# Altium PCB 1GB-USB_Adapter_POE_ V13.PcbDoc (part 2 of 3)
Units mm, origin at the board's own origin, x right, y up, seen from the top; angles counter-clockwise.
Board outline 92 x 80 mm, 4 copper layers (Top Layer, Signal Layer 2, Signal Layer 3, Bottom Layer), stack 1.57 mm thick; 189 components, 102 nets, 551 pads, 429 vias.
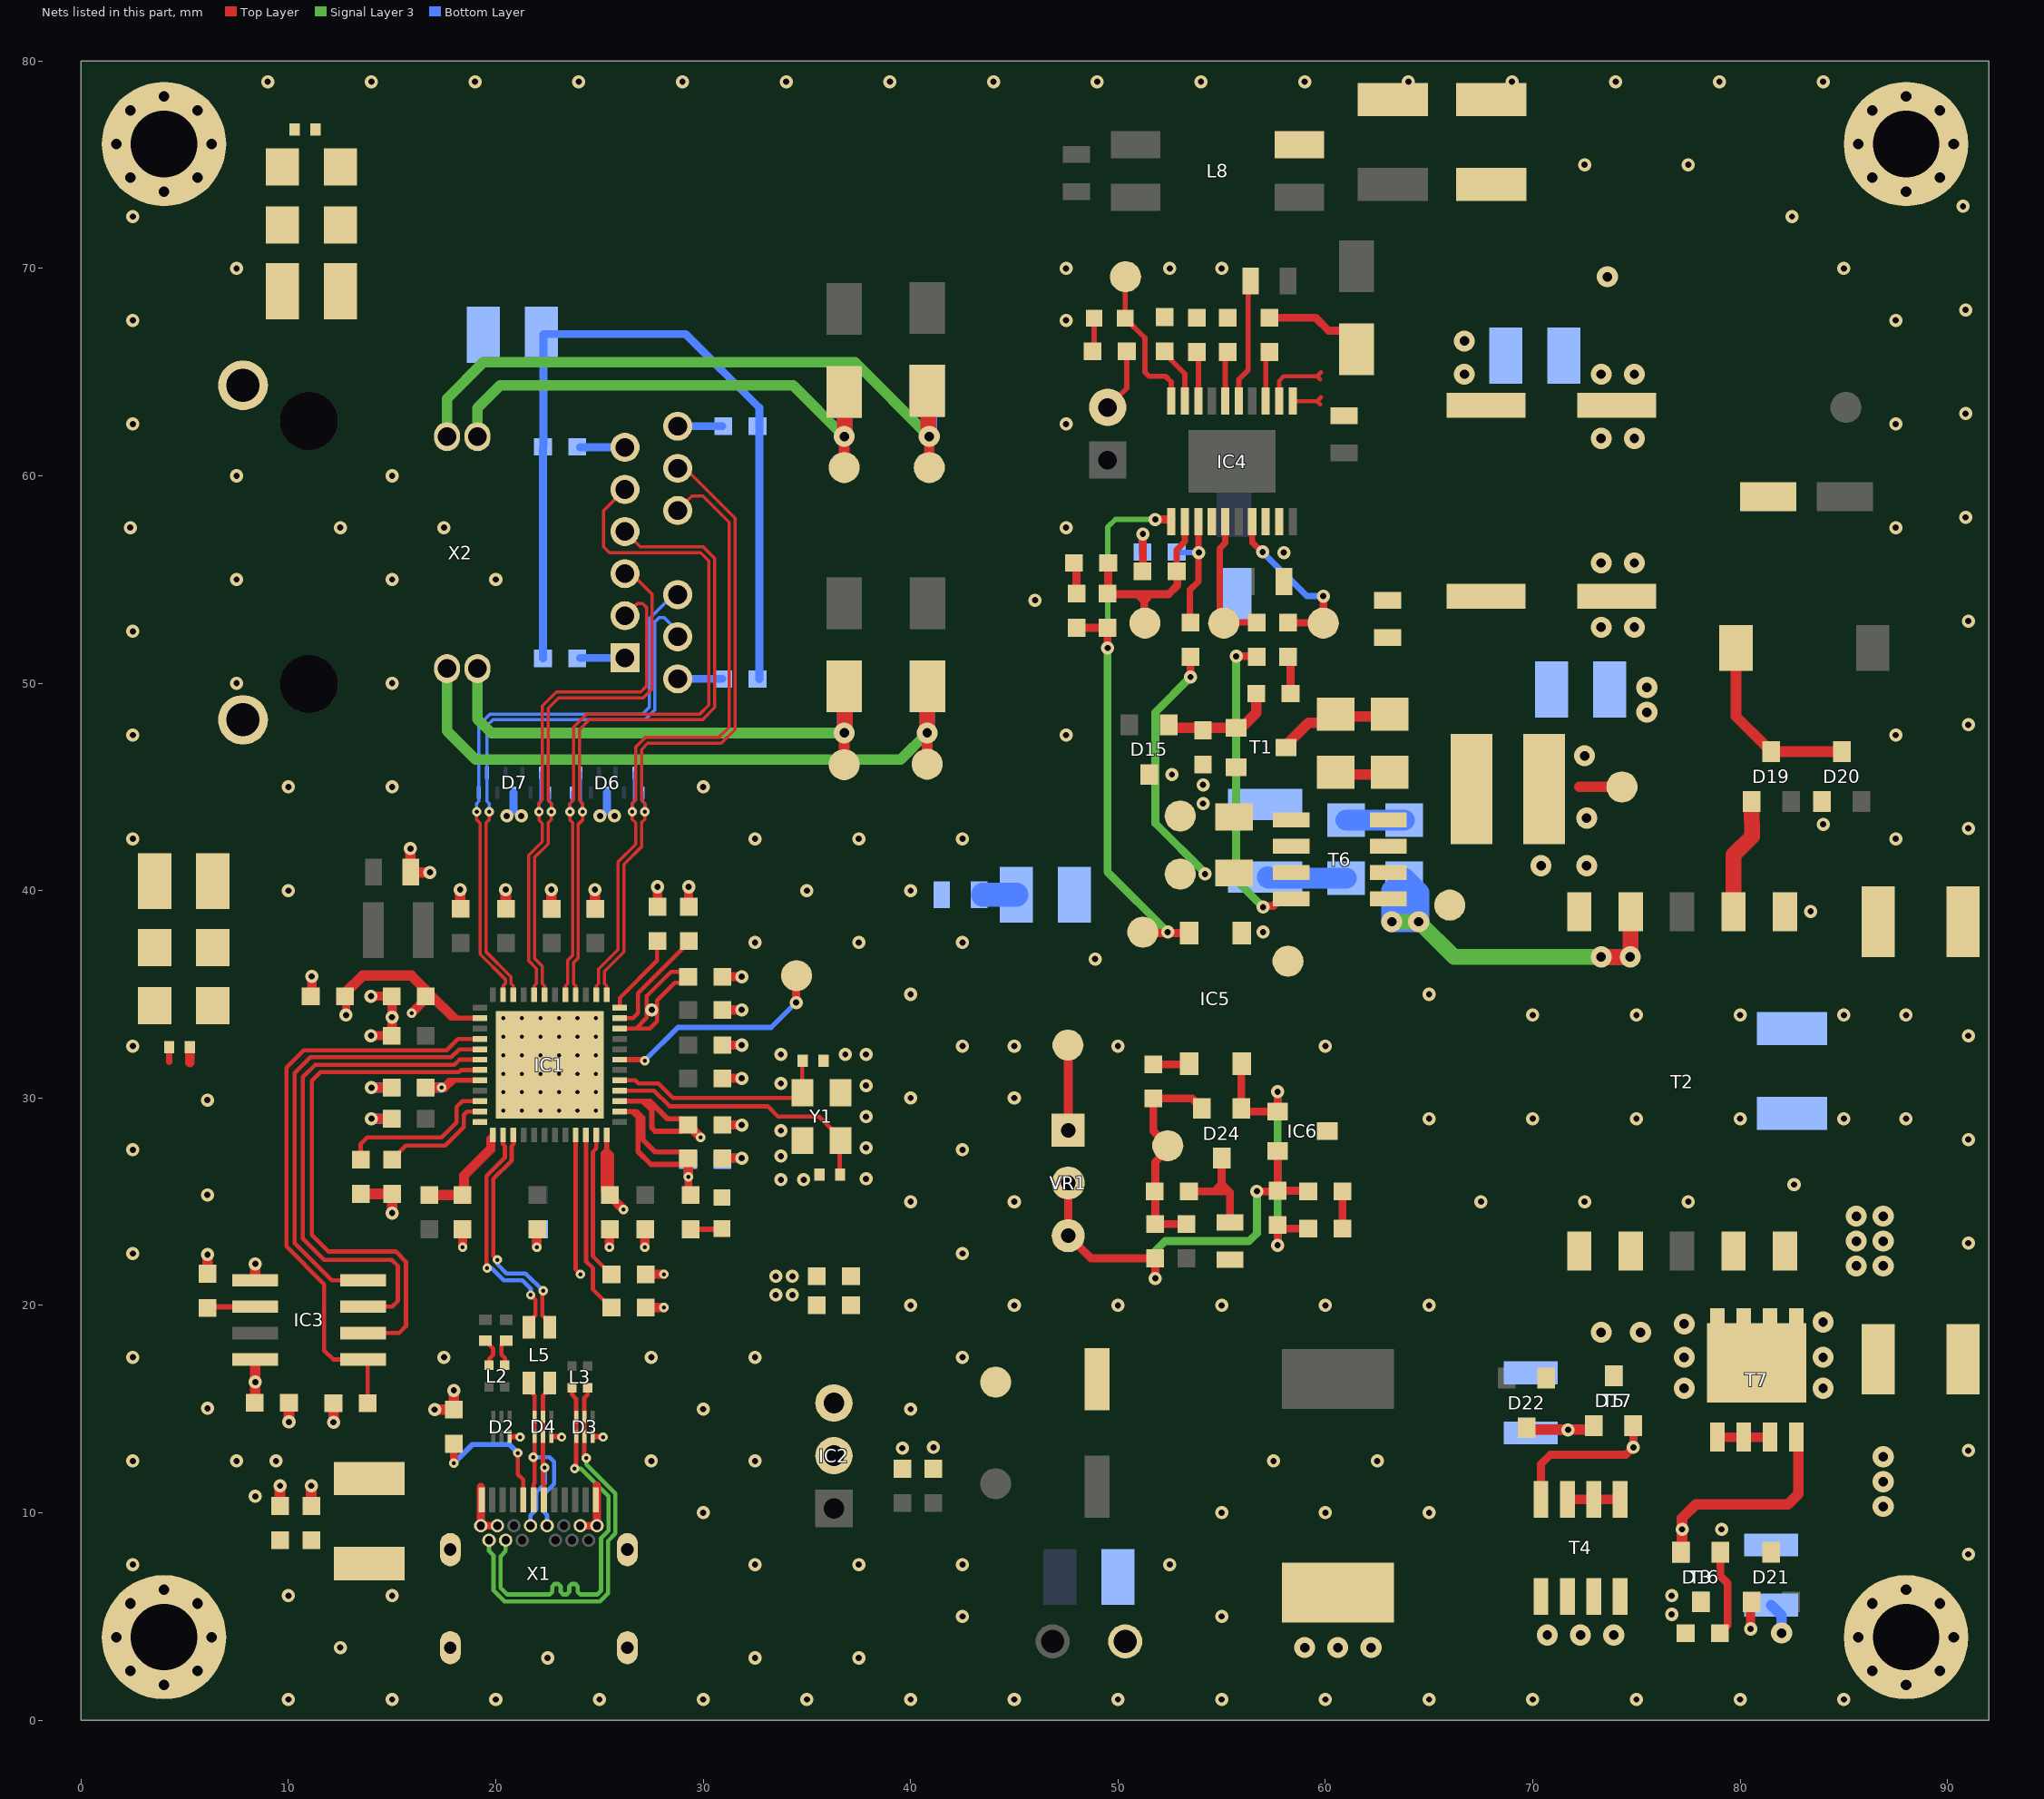
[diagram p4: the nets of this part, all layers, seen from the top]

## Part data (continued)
D1 D8 D9 D10 D11 D12 D13 D14: "DIODE, Schottky, 100V, 1A, SMA", Manufacturer=Diodes, Supplier Part Number 1=621-B1100-F, Temperature="-65°C ~ 150°C", Voltage=100V
D2 D3 D4: "DIODE, TVS Super Speed , 3.3V, DFN1210-6L", Manufacturer=Wurth, Supplier Part Number 1=710-824012823, Temperature="-55°C ~ 85°C", Voltage=3.3V
D5 D25: "LED 572NM GREEN 0603 SMD", Manufacturer=Wurth, Supplier Part Number 1=710-150060VS75020
D6 D7: "DIODE, TVS Super Speed , 5V, 8CH, 3.8x1.0mm", Manufacturer=Wurth, Supplier Part Number 1=710-824014885, Temperature="-55°C ~ 85°C", Voltage=5V/0.5pF
D15 D16 D17 D19 D20: "DIODE, Switching, 75V, 0.2A, SOT-23", Manufacturer=Onsemi, Supplier Part Number 1=863-BAS16LT1G, Temperature="-55°C ~ 150°C", Voltage=75V
D18 D23: "DIODE, TVS , 58V, 400W, Unidirection, SMA", Manufacturer=Diodes, Power=400W, Supplier Part Number 1=621-SMAJ58A-13-F, Temperature="-55°C ~ 150°C", Voltage=58V
D21 D22: "DIODE, ZENER, 12V, 300mW, SOT-23", Manufacturer=Diodes, Supplier Part Number 1=863-BZX84C12LT1G
D24: library part "BAV99 RF", "DIODE, Dual, 70V, 0.2A, SOT-23", Manufacturer="Taiwan Semi", Supplier Part Number 1=821-BAV99RF, Temperature="-55°C ~ 150°C", Voltage=70V
FB3: "Ferrite Bead 120R @ 100MHz / 0603 / 2.0A", Manufacturer=Wurth, Supplier Part Number 1=710-742792625
FB4: "Ferrite Bead 22R @ 100MHz / 0805 / 6.0A", Manufacturer=Wurth, Supplier Part Number 1=710-742792021
H1 H2 H3 H4: Manufacturer=xxxx, Temperature="-55 to 150 °C"
IC1: "IC USB3.1 to 1G Ethernet Bridge, 3.3V, QFN-48", Manufacturer=Microchip, Supplier Part Number 1=579-LAN7800/Y9X
IC2: "DC/DC Converters, Non-Isolated, 7-28Vin, 3.3Vout, 3.3W", Manufacturer=Wurth, Supplier Part Number 1=710-173010378
IC3: "IC EEPROM, SPI, 4kb, 16MHz, 1.8-5.5V, SO-8", Manufacturer=Microchip, Supplier Part Number 1=579-93AA66C-I/SN
IC4: "IC IEEE 802.3at POE/DC-DC, HTSSOP20", Manufacturer=TI, Supplier Part Number 1=595-TPS23754PWP-1
IC5: "OPTOISOLATOR, 3.75kV, 50mA, SOP-4", Manufacturer=Wurth, Supplier Part Number 1=710-140356145100
IC6: "IC VREF SERIES 2.495V", Manufacturer=TI, Supplier Part Number 1=595-TL431ACDBZR
L1: "Inductor 3.3uH / 4828 / 2.15A", Inductance=3.3uH, Manufacturer=Wurth, Supplier Part Number 1=732-1097-1-ND
L2 L3: "Common Mode Chokes 60R @ 100MHz / 1x1.2mm / 600mA", Manufacturer=Wurth, Supplier Part Number 1=710-7442335600
L4: "Inductor 3.3uH / 3015 / 1.5A", Inductance=3.3uH, Manufacturer=Wurth, Supplier Part Number 1=710-74404032033
L5: "Common Mode Chokes 90R @ 100MHz / 1206 / 370mA", Manufacturer=Wurth, Supplier Part Number 1=710-744232090
L6: "Inductor 22uH / 1280 / 4.1A", Inductance=22uH, Manufacturer=Wurth, Supplier Part Number 1=710-744770122
L7: "Inductor 1mH / 7332 / 0.2A", Inductance=1mH, Manufacturer=Wurth, Supplier Part Number 1=710-74477830
L8: "Common Mode Chokes 2x1000uH / 9.2x6mm / 800mA", Manufacturer=Wurth, Supplier Part Number 1=710-744222
L9: "Inductor 4.7uH / 4018 / 1.7A", Inductance=4.7uH, Manufacturer=Wurth, Supplier Part Number 1=710-74404042047
R1 R4: "RES, 330 ohm, 1%, 0.1W, 0603", Manufacturer=Yageo, Power_W=0.1, Supplier Part Number 1=603-RC0603FR-07330RL, Tolerance_%=1%
R2: "RES, 5.1kohm, 1%, 0.1W, 0603", Manufacturer=Yageo, Power_W=0.1, Supplier Part Number 1=603-RC0603FR-075K1L, Tolerance_%=1%
R3 R9 R10 R13: "RES, 75 ohm, 1%, 0.1W, 0603", Manufacturer=Yageo, Power_W=0.1, Supplier Part Number 1=603-RC0603FR-0775RL, Tolerance_%=1%
R5 R6 R8 R12 R14 R17 R18 R38 R42: "RES, 10kohm, 1%, 0.1W, 0603", Manufacturer=Yageo, Power_W=0.1, Supplier Part Number 1=603-RC0603FR-0710KL, Tolerance_%=1%
R7: "RES, 2kohm, 1%, 0.1W, 0603", Manufacturer=Yageo, Power_W=0.1, Supplier Part Number 1=603-RC0603FR-072KL, Tolerance_%=1%
R11: "RES, 12kohm, 1%, 0.1W, 0603", Manufacturer=Yageo, Power_W=0.1, Supplier Part Number 1=603-RC0603FR-0712KL, Tolerance_%=1%
R15: "RES, 0 ohm, 1%, 0.1W, 0603", Manufacturer=Yageo, Power_W=0.1, Supplier Part Number 1=603-RC0603FR-070RL, Tolerance_%=1%
R16 R29: "RES, 2k ohm, 1%, 0.5W, 1210", Manufacturer=YAGEO, Power_W=0.5W, Supplier Part Number 1=603-RC1210FR-072KL, Tolerance_%=1
R19 R20: "RES, 0 ohm, 1%, 0.063W, 0402", Manufacturer=Yageo, Power_W=0.063, Supplier Part Number 1=603-RC0402FR-070RL, Tolerance_%=1%
R27: "RES, 24.9kohm, 1%, 0.1W, 0603", Manufacturer=Yageo, Power_W=0.1, Supplier Part Number 1=603-RC0603FR-0724K9L, Tolerance_%=1%
R28: "RES, 69.8kohm, 1%, 0.1W, 0603", Manufacturer=Yageo, Power_W=0.1, Supplier Part Number 1=603-RC0603FR-0769K8L, Tolerance_%=1%
R30: "RES, 80.6kohm, 1%, 0.1W, 0603", Manufacturer=Yageo, Power_W=0.1, Supplier Part Number 1=603-RC0603FR-0780K6L, Tolerance_%=1%
R31: "RES, 63.4kohm, 1%, 0.1W, 0603", Manufacturer=Yageo, Power_W=0.1, Supplier Part Number 1=603-RC0603FR-0763K4L, Tolerance_%=1%
R32: "RES, 10 ohm, 1%, 0.1W, 0603", Manufacturer=Yageo, Power_W=0.1, Supplier Part Number 1=311-10.0HRCT-ND, Tolerance_%=1%
R33: "RES, 63.4 ohm, 1%, 0.125W, 0805", Manufacturer=Yageo, Power_W=0.125, Supplier Part Number 1=603-RC0805FR-0763R4L, Tolerance_%=1%
R34: "RES, 1kohm, 1%, 0.1W, 0603", Manufacturer=Yageo, Power_W=0.1, Supplier Part Number 1=603-RC0603FR-071KL, Tolerance_%=1%
R35: "RES, 0.12 ohm, 1%, 1W, 1206", Manufacturer=YAGEO, Power_W=1, Supplier Part Number 1=311-.12LWCT-ND, Tolerance_%=-
R36: "RES, 49.9 ohm, 1%, 0.1W, 0603", Manufacturer=Yageo, Power_W=0.1, Supplier Part Number 1=603-RC0603FR-0749R9L, Tolerance_%=1%
R37: "RES, 348 ohm, 1%, 0.1W, 0603", Manufacturer=Yageo, Power_W=0.1, Supplier Part Number 1=603-RC0603FR-07348RL, Tolerance_%=1%
R39: "RES, 2.49kohm, 1%, 0.1W, 0603", Manufacturer=Yageo, Power_W=0.1, Supplier Part Number 1=603-RC0603FR-072K49L, Tolerance_%=1%
R40: "RES, 1.5kohm, 1%, 0.1W, 0603", Manufacturer=Yageo, Power_W=0.1, Supplier Part Number 1=603-RC0603FR-071K5L, Tolerance_%=1%
R41: "RES, 41.2kohm, 1%, 0.1W, 0603", Manufacturer=Yageo, Power_W=0.1, Supplier Part Number 1=603-RC0603FR-0741K2L, Tolerance_%=1%
R43: "RES, 6.2kohm, 1%, 0.1W, 0603", Manufacturer=Yageo, Power_W=0.1, Supplier Part Number 1=603-RC0603JR-076K2L, Tolerance_%=1%
T1: "MOSFET, P-CH, 20V, 0.69A, SOT-23", Manufacturer=Vishay, Supplier Part Number 1=781-SI2325DS-E3
T2: "Trans, POE, 30W, SMT", Manufacturer=Wurth, Supplier Part Number 1=710-750311320
T3 T5: "Transistor, NPN, 80V, 0.5A, SOT-23", Manufacturer=Onsemi, Supplier Part Number 1=863-MMBTA06LT1G
T4: "MOSFET, N-CH, 60V, 8.5A, SO-8", Manufacturer=Vishay, Supplier Part Number 1=781-SI4850EY-GE3
T6: "MOSFET, N-CH, 150V, 3.7A, SO-8", Manufacturer=Vishay, Supplier Part Number 1=781-SI4848DY-GE3
T7: "MOSFET, N-CH, 80V, 12.5A, PowerPAK-SO-8", Manufacturer=Vishay, Supplier Part Number 1=781-SI7852DP-GE3
TP1 TP2 TP3 TP4 TP5 TP6 TP7 TP8 TP9 TP10 TP11 TP12 TP13 TP14 TP15 TP16 TP17 TP18 TP20 TP21: library part "TP / 1.5mm", "Test Point, SMT, Miniature"
VR1: "Trimmer, 20kohm, 10%, 0.5W, 4.83x9.53x10.03mm", Manufacturer=Bourns, Power_W=0.5, Supplier Part Number 1=0141-0263-1, Tolerance_%=10%
X1: "CON, USB, Type C, Female, 24P, Hor, SMT", Manufacturer=Wurth, Supplier Part Number 1=710-632723300011
X2: "CON, Ethernet, Int Magnetics, POE+, 8P, 1x1 Tab-Up, INS", Manufacturer=Wurth, Supplier Part Number 1=710-7499511001A
X3: "CON, Terminal Block, Screw, 2P, P3.5mm, 10A, INS", Manufacturer=Wurth, Supplier Part Number 1=710-691214110002S
X4: "CON, Header, Male, 2P, P2.54mm, Straight, INS", Manufacturer=Wurth, Supplier Part Number 1=710-61300211121
Y1: "Crystal / 25MHz / 18pF / 30ppm", Load Capacitance=18pF, Manufacturer=Wurth, Package=3.2x2.5x0.8mm, Supplier Part Number 1=710-830055299

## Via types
v1: diameter 0.635, hole 0.3, Top Layer to Bottom Layer, tented both sides, 260 vias
v2: diameter 0.45, hole 0.2, Top Layer to Bottom Layer, tented both sides, 80 vias
v3: diameter 1.016, hole 0.457, Top Layer to Bottom Layer, tented both sides, 55 vias
v4: diameter 1.016, hole 0.508, Top Layer to Bottom Layer, 32 vias
v5: diameter 0.762, hole 0.3, Top Layer to Bottom Layer, tented both sides, 2 vias

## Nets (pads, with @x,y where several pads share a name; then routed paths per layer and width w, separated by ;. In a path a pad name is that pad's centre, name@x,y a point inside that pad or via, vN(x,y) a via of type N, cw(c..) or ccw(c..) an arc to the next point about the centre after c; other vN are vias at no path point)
3V3_Board: C16.1 C17.2 C18.1 C21.1 C22.1 C23.1 C24.1 C26.2 C27.1 C40.1 C50.1 C51.1 IC1.14 IC1.20 IC1.36 IC1.38 IC1.39 IC1.46 IC2.3 IC3.8 R4.1 R5.1 R6.1 R8.2 | length 58.1
  Top Layer w0.2: IC1.46@25.975,33.35 26.763,33.35 ; C24.1@28.955,29 C24.1@29.255,28.7 ; C18.1@28.955,35.55 28.63,35.55 27.78,34.7 27.78,33.7 27.43,33.35 26.763,33.35 ; C18.1@29.025,36.08 28.445,36.08 27.28,34.915 27.28,33.867 26.763,33.35
  Top Layer w0.25: C21.1@16.606,30.5 16.706,30.4 17.556,30.4 18.006,30.85 ; C16.1@16.713,34.75 16.93,34.75 17.83,33.85 18.13,33.85 ; C21.1@16.865,30.6 17.482,30.6 17.732,30.85 18.006,30.85 ; C16.1@16.873,35.107 18.13,33.85 ; IC1.20@19.225,30.85 18.006,30.85 ; IC1.14@19.225,33.85 18.13,33.85 ; C22.1@25.18,25.526 25.18,27.33 25.35,27.5 ; C22.1@25.28,25.526 C22.1@25.35,25.456 ; C22.1@25.35,25.356 C22.1@25.35,25.456 ; IC1.36@25.35,28.225 25.35,27.5 ; C22.1@25.48,25.325 C22.1@25.35,25.456 ; C22.1@25.58,25.6 25.58,27.27 25.35,27.5 ; C22.1@25.35,25.456 25.35,27.5
  Top Layer w0.254: IC1.38@25.975,29.35 26.58,29.35 ; IC1.39@25.975,29.85 27.08,29.85 ; C24.1@28.955,29 28.28,29 27.43,29.85 27.08,29.85 ; C24.1@29.255,28.7 28.955,28.4 27.68,28.4 27.525,28.555 27.525,29.405 27.08,29.85 ; 26.58,29.35 26.856,29.075 26.856,27.424 27.48,26.8 28.955,26.8 29.255,27.1 28.955,27.4 27.68,27.4 27.08,28 27.08,29.045 26.775,29.35 26.58,29.35
  Top Layer w0.381: R4.1@29.28,25.445 v2(29.28,26.2)
  Top Layer w0.4: v1(12.78,34) C17.2@12.78,34.905
  Top Layer w0.45: v2(15.94,34.095) C16.1@16.522,34.677 ; C22.1@25.58,25.2 v2(26.162,24.618) ; R6.1@27.226,21.5 v2(28.1,21.5) ; C23.1@29.255,27.1 29.28,27.074 v2(29.28,26.2) ; R4.1@29.28,25.445 R4.1@29.4,25.325 ; C24.1@29.298,28.682 v2(29.88,28.1)
  Top Layer w0.5: C17.2@12.776,35.095 13.58,35.9 15.932,35.9 16.586,35.246 C16.1@16.586,34.91
  Top Layer w0.508: C40.1@8.369,15.305 C40.1@8.374,15.3 ; C40.1@8.4,15.331 v1(8.4,16.3) IC3.8@8.4,17.395 ; R8.2@13.5,25.374 R5.1@15,25.374 v1(15,24.45)
  Bottom Layer w0.45: v2(29.28,26.2) C51.1@29.28,26.974
  Bottom Layer w0.508: C50.1@16.605,30.5 v2(17.38,30.5)
  other v1: 33.5,20.5 34.3,20.5 33.5,21.4 34.3,21.4 27.52,34.25
AGND: C32.1 C34.2 C35.2 C39.2 C44.2 C45.2 C57.2 C58.2 C59.2 C60.2 C73.2 C78.1 D15.3 D20.1 D23.2 IC4.4 IC4.8 IC4.9 IC5.3 L9.2 R14.2 R28.1 R30.1 R31.1 R35.1 T1.2 T2.5 TP15.1 TP18.1 | length 2.6
  Top Layer w0.381: C60.2@51.2,55.426 v1(51.2,57.2)
  Bottom Layer w0.381: C59.2@51.187,56.338 51.187,57.187 v1(51.2,57.2)
  other v1: 70,34 75,34 80,34 85,34 88,34 65,35 48.9,36.7 57,38 83.4,39 87.5,42.5 84,43.2 54.1,44.2 54.1,45.1 52.6,45.6 47.5,47.5 87.5,47.5 46,54 58,56.3 47.5,57.5 87.5,57.5 47.5,62.5 87.5,62.5 47.5,67.5 87.5,67.5 47.5,70 52.5,70 55,70 85,70 82.5,72.5 72.5,75 77.5,75
  other v3: 75.5,48.6 75.5,49.8 73.3,52.7 74.9,52.7 73.3,55.8 74.9,55.8 73.3,61.8 74.9,61.8 73.3,64.9 74.9,64.9 73.6,69.6
EECLK: IC1.19 IC3.2 | length 26.1
  Top Layer w0.203: IC3.2@13.6,18.665 15.34,18.665 15.667,18.992 15.667,22.114 15.18,22.6 11.927,22.6 11.125,23.402 11.125,30.825 11.546,31.246 18.218,31.246 18.321,31.35 IC1.19@19.225,31.35
EECS: IC1.16 IC3.1 R18.1 | length 28.5
  Top Layer w0.203: R18.1@13.825,15.29 13.825,17.169 IC3.1@13.6,17.395 12.158,17.395 11.727,17.826 11.727,21.02 9.9,22.847 9.9,31.46 10.734,32.294 17.624,32.294 18.18,32.85 IC1.16@19.225,32.85
EEDI: IC1.17 IC3.4 | length 21.6
  Top Layer w0.203: IC3.4@13.6,21.205 12.1,21.205 10.3,23.005 10.3,31.2 11.063,31.963 17.843,31.963 18.23,32.35 IC1.17@19.225,32.35
EEDO: IC1.18 IC3.3 | length 25.3
  Top Layer w0.203: IC3.3@13.6,19.935 15,19.935 15.275,20.21 15.275,21.9 14.975,22.2 11.727,22.2 10.7,23.227 10.7,31 11.294,31.594 17.994,31.594 18.25,31.85 IC1.18@19.225,31.85
GND: C3.2 C4.2 C5.2 C6.2 C9.2 C10.2 C11.2 C12.2 C13.2 C14.2 C15.1 C16.2 C17.1 C18.2 C19.1 C20.2 C21.2 C22.2 C23.2 C24.2 C25.1 C26.1 C27.2 C28.2 C29.2 C30.1 C31.1 C32.2 C36.2 C37.2 C38.2 C40.2 C41.2 C42.2 C43.2 C46.2 C47.2 C48.2 C49.2 C50.2 C51.2 C55.2 C56.2 C64.2 C74.2 C75.2 D2.3 D3.3 D4.3 D5.1 D6.3 D7.3 D21.1 D22.1 FB4.2 IC1.49 IC2.2 IC3.5 IC6.3 R1.1 R2.2 R7.2 R11.2 R12.2 R17.2 R18.2 R19.2 R20.2 T4.1 T4.2 T4.3 T7.1 T7.2 T7.3 TP12.1 TP20.1 VR1.1 X1.A1 X1.A12 X1.B1 X1.B12 X3.2 Y1.2 Y1.4 | length 56.5
  Top Layer w0.254: 20.775,13.675 21.15,13.675 v2(21.175,13.65) ; 22.775,13.675 23.15,13.675 v2(23.175,13.65) ; 24.775,13.675 25.15,13.675 v2(25.175,13.65)
  Top Layer w0.381: 19.275,11.25 X1.B12@19.275,9.375 X1.B12@20.075,9.375 ; X1.B1@24.075,9.375 X1.B1@24.875,9.375 24.875,11.31
  Top Layer w0.45: 5.25,31.693 R19.2@5.25,32.454 ; C17.1@11.125,34.91 v1(11.125,35.862) ; v1(13.982,33.005) 14.935,33.005 14.998,33.068 v1(14.998,33.894) C16.2@14.998,34.846 ; v1(13.982,34.91) C16.2@14.935,34.91 ; v1(14.002,29) C3.2@14.955,29 ; v1(14.002,30.5) C21.2@14.955,30.5 ; v2(18.4,22.8) C9.2@18.4,23.674 ; v2(21.98,22.8) C4.2@21.98,23.674 ; v2(25.48,22.8) C22.2@25.48,23.674 ; v2(27.18,22.8) R11.2@27.18,23.674 ; R12.2@27.226,19.9 v2(28.1,19.9) ; C29.2@27.8,39.231 v1(27.8,40.183) ; R7.2@29.3,39.231 v1(29.3,40.183) ; C23.2@30.906,27.1 C23.2@30.926,27.1 v1(31.858,27.1) ; C24.2@30.906,28.7 C24.2@30.926,28.7 v1(31.858,28.7) ; C5.2@30.906,30.95 C5.2@30.926,30.95 v1(31.858,30.95) ; C6.2@30.906,32.55 C6.2@30.926,32.55 v1(31.858,32.55) ; C20.2@30.906,34.25 v1(31.858,34.25) ; C18.2@30.906,35.85 C18.2@30.926,35.85 v1(31.858,35.85) ; TP20.1@47.587,32.55 47.6,32.537 VR1.1@47.6,28.44 ; T4.3@71.665,10.64 T4.2@72.935,10.64 T4.1@74.205,10.64 ; T7.1@78.895,13.642 T7.2@80.165,13.642 T7.3@81.435,13.642 ; v1(80.5,4.4) 80.5,5.65 D21.1@80.55,5.7
  Top Layer w0.508: R17.2@6.1,21.525 v1(6.1,22.45) ; IC3.5@8.4,21.205 v1(8.4,22) ; R1.1@9.575,10.171 9.6,10.196 R1.1@9.6,10.325 v1(9.6,11.3) ; R1.1@9.58,10.225 v1@9.58,11.15 ; v1(10.025,14.376) C40.2@10.025,15.3 ; C19.1@11.075,10.171 11.1,10.196 C19.1@11.1,10.325 v1(11.1,11.3) ; C19.1@11.08,10.225 v1@11.08,11.15 ; v1(12.174,14.365) R18.2@12.174,15.29 ; C15.1@15.88,41.1 v1(15.88,42.024) ; C15.1@15.898,40.879 v1(16.823,40.879) ; v1(17.051,14.975) R2.2@17.975,14.975 v1(17.975,15.9) ; C13.2@18.28,39.125 v1(18.28,40.05) ; C12.2@20.48,39.125 v1(20.48,40.05) ; C11.2@22.68,39.125 v1(22.68,40.05) ; C10.2@24.78,39.125 v1(24.78,40.05)
  Bottom Layer w0.4: 20.856,43.836 D7.3@20.856,44.714 ; 25.356,43.836 D6.3@25.356,44.714
  Bottom Layer w0.45: v2(21.98,22.8) C47.2@21.98,23.474 ; C51.2@31.006,27.1 v1(31.858,27.1)
  Bottom Layer w0.508: v1(14.002,29) C46.2@14.777,29 ; v1(14.002,30.5) C50.2@14.777,30.5
  other v1: 42.5,5 55,5 32.5,7.5 37.5,7.5 42.5,7.5 52.5,7.5 30,10 55,10 60,10 65,10 8.4,10.795 7.5,12.5 9.4,12.5 27.5,12.5 32.5,12.5 57.5,12.5 62.5,12.5 39.6,13.114 41.1,13.15 30,15 40,15 6.1,15.036 17.5,17.5 27.5,17.5 32.5,17.5 42.5,17.5 40,20 45,20 50,20 55,20 60,20 65,20 42.5,22.5 40,25 45,25 67.5,25 72.5,25 77.5,25 6.096,25.325 82.599,25.825 33.747,26.058 34.85,26.058 37.85,26.1 33.747,27.197 42.5,27.5 37.85,27.6 33.747,28.425 65,29 70,29 75,29 80,29 85,29 88,29 37.85,29.1 6.096,29.9 40,30 45,30 37.85,30.6 33.747,30.7 33.747,32.1 36.85,32.1 37.85,32.1 42.5,32.5 45,32.5 50,32.5 60,32.5 40,35 32.5,37.5 37.5,37.5 42.5,37.5 10,40 35,40 40,40 32.5,42.5 37.5,42.5 42.5,42.5 20.53,43.6 21.23,43.6 25.03,43.6 25.73,43.6 10,45 15,45 30,45 15,50 15,55 20,55 12.5,57.5 17.5,57.5 15,60
  other v2: 20.364,29.384 21.257,29.384 22.15,29.384 23.044,29.384 23.937,29.384 24.83,29.384 20.364,30.277 21.257,30.277 22.15,30.277 23.044,30.277 23.937,30.277 24.83,30.277 20.364,31.17 21.257,31.17 22.15,31.17 23.044,31.17 23.937,31.17 24.83,31.17 20.364,32.064 21.257,32.064 22.15,32.064 23.044,32.064 23.937,32.064 24.83,32.064 20.364,32.957 21.257,32.957 22.15,32.957 23.044,32.957 23.937,32.957 24.83,32.957 20.364,33.85 21.257,33.85 22.15,33.85 23.044,33.85 23.937,33.85 24.83,33.85
LED2: IC1.24
LED3: IC1.33 | length 6.8
  Top Layer w0.203: IC1.33@23.85,28.225 23.85,21.73 v2(24.08,21.5)
NetC1_1: C1.1 R3.2 R9.2 R10.2 R13.2 | length 40.5
  Bottom Layer w0.381: R10.2@22.274,51.2 R9.2@22.274,61.36 ; R9.2@22.293,61.502 22.293,66.836 29.151,66.836 32.707,63.28 32.707,62.4 R13.2@32.707,50.199
NetC2_1: C2.1 C65.1 T1.3 | length 5.6
  Top Layer w0.508: T1.3@58.043,46.957 59.182,48.096 60.196,48.096 60.494,48.394 C65.1@63.04,48.394
NetC2_2: C2.2 C65.2 C76.1 T2.2 T6.5 T6.6 T6.7 T6.8 TP9.1 | length 26.5
  Top Layer w0.508: C2.2@60.554,45.6 C65.2@63.1,45.6
  Top Layer w0.762: v3(73.3,36.8) v3(74.7,36.8) ; v3@74.72,36.82 T2.2@74.72,38.98
  Signal Layer 3 w0.762: v3(63.2,38.5) v3(64.5,38.5) 66.2,36.8 v3(73.3,36.8) v3(74.7,36.8)
  Bottom Layer w1.016: C76.1@63.8,40.6 63.8,38.55 63.85,38.5 ; C76.1@63.8,40.6 63.2,40 v3(63.2,38.5) 63.85,38.5 ; C76.1@63.8,40.6 64.5,39.9 v3(64.5,38.5) 63.85,38.5
NetC7_1: C7.1 L2.3 | length 1.3
  Top Layer w0.206: L2.3@20.445,17.125 20.445,17.453 20.27,17.628 20.27,18.07 C7.1@20.5,18.3
NetC8_1: C8.1 L2.2 | length 1.4
  Top Layer w0.206: C8.1@19.47,18.3 19.87,17.9 19.87,17.628 19.695,17.453 L2.2@19.695,17.125
NetC9_1: C9.1 FB3.1 IC1.25 | length 8.6
  Top Layer w0.254: C9.1@18.355,25.351 C9.1@18.38,25.325 ; C9.1@18.53,25.475 18.355,25.651 18.355,26.3 19.661,27.606 19.661,28.036 IC1.25@19.85,28.225 19.85,27.489 18.58,26.219 C9.1@18.58,25.525
  Top Layer w0.305: C9.1@18.38,25.325 18.53,25.475 C9.1@18.58,25.525
  Top Layer w0.508: FB3.1@16.78,25.325 C9.1@18.38,25.325
NetC29_1: C29.1 IC1.48 | length 4
  Top Layer w0.2: IC1.48@25.975,34.35 25.975,34.825 27.78,36.63 C29.1@27.78,37.574
NetC30_2: C30.2 IC1.40 Y1.1 | length 13.2
  Top Layer w0.203: IC1.40@25.975,30.35 27.629,30.35 28.379,29.6 33.105,29.6 33.605,29.1 35.58,29.1 Y1.1@36.48,28.2 ; C30.2@36.58,26.3 Y1.1@36.58,28.1
NetC31_2: C31.2 IC1.41 Y1.3 | length 10.7
  Top Layer w0.203: IC1.41@25.975,30.85 26.73,30.85 26.88,30.7 27.845,30.7 28.545,30 Y1.3@34.78,30 ; Y1.3@34.78,30.275 C31.2@34.78,31.8
NetC33_1: C33.1 D15.1 R14.1 T1.1 | length 5.3
  Top Layer w0.508: D15.1@52.566,47.85 T1.1@55.7,47.85 55.95,47.85 56.674,48.575 C33.1@56.674,49.5
NetC33_2: C33.2 R15.2 | length 1.7
  Top Layer w0.381: R15.2@58.2,51.274 58.32,51.154 C33.2@58.32,49.654
NetC34_1: C34.1 C35.1 C39.1 C44.1 C54.1 C71.1 D18.2 IC4.11 IC4.12 L1.1 L8.3 R27.1 | length 9.2
  Top Layer w0.203: IC4.12@57.775,63.6 57.775,64.585 57.99,64.8 59.6,64.8 ; IC4.11@58.425,63.6 59.6,63.6 ; 59.75,64.65 59.6,64.8 ; 59.789,63.789 59.6,63.6 ; 59.789,64.989 59.6,64.8 ; 59.6,63.6 59.75,63.45 59.6,63.6
  Top Layer w0.381: R27.1@57.3,67.626 59.531,67.626 60.156,67 D18.2@61,67
  other v3: 66.7,64.9 66.7,66.5
NetC45_1: C45.1 L1.2 T2.1 TP6.1 | length 2.1
  Top Layer w0.508: 72.24,45 TP6.1@74.3,45
  other v3: 70.4,41.2 72.6,41.2 72.6,43.5 72.5,46.5
NetC52_1: C52.1 D21.3 R16.2 T3.1 | length 4.2
  Top Layer w0.381: C52.1@79.026,4.2 79.4,4.574 79.4,6.6 79.05,6.95 T3.1@79.05,8.1
  other v1: 79.1,9.2
NetC52_2: C52.2 D16.3 L6.1 R16.1 T2.6 T2.7 T3.3 T4.5 T4.6 T4.7 T4.8 | length 1.6
  Bottom Layer w0.508: R16.1@81.5,5.55 82,5.05 v3(82,4.2)
  other v1: 76.7,5.1 76.7,6
  other v3: 59,3.5 60.6,3.5 62.2,3.5 70.7,4.1 72.3,4.1 73.9,4.1 86.9,10.3 86.9,11.5 86.9,12.7 85.6,21.9 86.9,21.9 85.6,23.1 86.9,23.1 85.6,24.3 86.9,24.3
NetC59_1: C59.1 IC4.3 R34.1 | length 6.1
  Top Layer w0.305: R34.1@53.475,52.9 53.475,54.505 53.875,54.905 IC4.3@53.875,57.8
  Bottom Layer w0.254: C59.1@52.904,56.3 v1(53.9,56.3)
NetC60_1: C60.1 IC4.2 R37.1 R40.1 TP14.1 | length 10.3
  Top Layer w0.305: C60.1@52.826,55.4 52.826,56.426 53.225,56.825 IC4.2@53.225,57.8
  Top Layer w0.381: R40.1@49.43,54.295 50.935,54.295 ; R40.1@49.525,54.351 R37.1@49.525,55.8 ; TP14.1@51.3,52.9 51.261,52.939 51.261,53.968 ; C60.1@52.859,55.387 52.859,54.714 52.44,54.295 51.588,54.295 ; 50.935,54.295 51.588,54.295 ; 50.935,54.295 51.261,53.968 ; 51.261,53.968 51.588,54.295
NetC61_1: C61.1 R37.2 | length 1.3
  Top Layer w0.381: C61.1@48,54.325 R37.2@48,55.674
NetC61_2: C61.2 IC4.1 IC5.4 R40.2 TP17.1 | length 28.6
  Top Layer w0.381: C61.2@48,52.674 R40.2@49.5,52.674 v1(49.5,51.7) ; TP17.1@51.25,37.95 IC5.4@53.43,37.95 ; v1(51.8,57.9) IC4.1@52.566,57.9 ; IC4.1@52.566,57.7 IC4.1@52.575,57.709
  Signal Layer 3 w0.254: v1(49.5,51.7) 49.5,57.525 49.875,57.9 v1(51.8,57.9)
  Signal Layer 3 w0.381: v1(49.5,51.7) 49.5,40.9 v1(52.4,38)
NetC62_1: C62.1 D24.1 IC5.2 IC6.1 R42.1 | length 14.4
  Top Layer w0.381: D24.1@55.95,29.5 IC5.2@55.95,31.63 ; D24.1@56.1,29.35 IC6.1@57.7,29.35 v1(57.7,30.3) ; v1(57.7,22.9) C62.1@57.7,23.874 ; C62.1@57.874,23.7 R42.1@59.174,23.7
  Signal Layer 3 w0.381: v1(57.7,22.9) v1(57.7,30.3)
NetC62_2: C62.2 C63.2 IC6.2 R41.2 VR1.2 VR1.3 | length 21.2
  Top Layer w0.381: VR1.2@47.6,25.9 VR1.3@47.6,23.36 48.686,22.274 R41.2@51.8,22.274 v1(51.8,21.3) ; v1(56.7,25.5) 57.675,25.5 C62.2@57.7,25.525 ; IC6.2@57.7,27.45 C62.2@57.7,25.525 ; C63.2@59.149,25.525 C62.2@57.7,25.525
  Signal Layer 3 w0.381: v1(51.8,21.3) 51.8,22.625 52.275,23.1 56.325,23.1 56.7,23.475 v1(56.7,25.5)
NetC63_1: C63.1 R42.2 | length 1.8
  Top Layer w0.381: R42.2@60.825,23.7 C63.1@60.825,25.5
NetC64_1: C64.1 D24.3 R38.2 | length 5.7
  Top Layer w0.381: R38.2@53.425,25.5 54.65,25.5 ; D24.3@55,27.1 55,25.85 ; C64.1@55.4,24 55.4,25.45 55.35,25.5 ; 54.65,25.5 55.35,25.5 ; 54.65,25.5 55,25.85 ; 55,25.85 55.35,25.5
NetC76_2: C76.2 C77.1 | length 2.8
  Bottom Layer w1.016: C77.1@61,43.4 C76.2@63.8,43.4
NetC77_2: C77.2 L9.1 | length 3.8
  Bottom Layer w1.016: L9.1@57.2,40.65 57.25,40.6 C77.2@61,40.6
NetC78_2: C78.2 FB4.1 | length 1.6
  Bottom Layer w1.143: FB4.1@43.5,39.8 C78.2@45.1,39.8
NetD5_2: D5.2 R4.2 | length 1.5
  Top Layer w0.254: R4.2@29.4,23.674 30.874,23.674 D5.2@30.9,23.7
NetD16_1: D16.1 T3.2 T7.4 | length 11.8
  Top Layer w0.508: T3.2@77.262,7.971 77.198,7.971 77.198,9.741 77.86,10.403 82.303,10.403 82.805,10.905 T7.4@82.805,13.442
  Bottom Layer w0.508: D16.1@77.198,7.908 D16.1@77.2,7.909 ; v1(77.2,9.2) D16.1@77.2,7.909 ; D16.1@77.262,7.971 D16.1@77.2,7.909
NetD17_1: D17.1 T4.4 T5.2 | length 8.6
  Top Layer w0.381: T4.4@70.395,10.64 70.395,12.345 70.85,12.8 74.5,12.8 v1(74.85,13.15) T5.2@74.85,14.2
  Bottom Layer w0.381: v1(74.85,13.15) D17.1@74.85,14.2
NetD17_3: D17.3 R29.1 T2.9 T2.10 T5.3 T7.5 T7.6 T7.7 T7.8 T7.9
  other v3: 77.3,16 84,16 77.3,17.5 84,17.5 73.3,18.7 75.2,18.7 77.3,19.1 84,19.2
NetD19_1: D19.1 T2.4 | length 5.4
  Top Layer w0.762: T2.4@79.68,38.98 79.68,41.723 80.569,42.612 D19.1@80.556,44.047
NetD19_3: D19.3 D20.3 L7.2 | length 9.1
  Top Layer w0.508: L7.2@79.8,51.7 79.8,48.4 81.254,46.946 81.329,46.946 81.5,46.775 D19.3@81.5,46.7 D20.3@84.9,46.7
NetD22_3: D22.3 R29.2 T5.1 | length 5.1
  Top Layer w0.127: T5.1@72.95,14.2 T5.1@73.014,14.01
  Top Layer w0.508: D22.3@69.939,14.009 71.7,14.009 v1@71.844,14.009 ; v1@71.744,14.01 T5.1@73.014,14.01
  Bottom Layer w0.508: R29.2@69.939,14.009 v1@71.7,14.009
  other v1: 71.7,14
NetD24_2: D24.2 R36.1 R38.1 R39.2 R41.1 TP16.1 | length 10.6
  Top Layer w0.381: TP16.1@52.4,27.517 51.8,26.917 R41.1@51.8,23.925 R36.1@53.3,23.925 ; TP16.1@52.4,27.615 TP16.1@52.4,27.7 51.7,28.4 R39.2@51.7,29.974 53.575,29.974 53.74,29.809 53.815,29.809 54.05,29.575 D24.2@54.05,29.5
NetD25_2: D25.2 R43.1 | length 1.5
  Top Layer w0.254: R43.1@48.85,66.075 D25.2@48.85,67.6
NetIC1_23: IC1.23 R5.2 | length 5.6
  Top Layer w0.203: R5.2@14.98,27.025 15.667,27.712 17.561,27.712 18.45,28.601 18.45,29.189 18.611,29.35 IC1.23@19.225,29.35
NetIC1_35: IC1.35 R6.2 | length 7.2
  Top Layer w0.203: IC1.35@24.85,28.225 24.85,27.575 24.68,27.405 24.68,22.374 R6.2@25.555,21.5
NetIC1_47: IC1.47 R7.1 | length 5.2
  Top Layer w0.2: IC1.47@25.975,33.85 26.61,33.85 26.856,34.095 26.856,35.053 R7.1@29.174,37.372
NetIC3_6: IC3.6 R17.1 | length 2.2
  Top Layer w0.254: R17.1@6.161,19.935 IC3.6@8.4,19.935
NetIC4_5: IC4.5 R32.1 TP11.1 | length 6.4
  Top Layer w0.305: TP11.1@54.9,53.1 54.9,56.5 55.175,56.775 IC4.5@55.175,57.8 ; TP11.1@55.125,52.925 R32.1@56.7,52.925
NetIC4_7: IC4.7 R15.1 TP10.1 | length 8.5
  Top Layer w0.305: IC4.7@56.475,57.8 56.473,56.794 v1(56.973,56.327)
  Top Layer w0.381: R15.1@58.2,52.925 TP10.1@59.9,52.9 v1(59.9,54.2)
  Bottom Layer w0.305: v1(56.973,56.327) 59.1,54.2 v1(59.9,54.2)
NetIC4_13: IC4.13 R27.2 | length 2.2
  Top Layer w0.254: IC4.13@57.125,63.6 R27.2@57.125,65.8
NetIC4_15: IC4.15 R33.2 | length 6.2
  Top Layer w0.254: IC4.15@55.825,63.6 55.825,64.65 56.275,65.1 R33.2@56.275,69.6
NetIC4_16: IC4.16 R31.2 | length 2.2
  Top Layer w0.254: IC4.16@55.175,63.6 R31.2@55.175,65.849
NetIC4_18: IC4.18 R30.2 | length 2.3
  Top Layer w0.254: IC4.18@53.875,63.6 R30.2@53.875,65.9
NetIC4_19: IC4.19 R28.2 | length 2.4
  Top Layer w0.254: R28.2@52.548,65.702 52.548,65.602 53.225,64.925 IC4.19@53.225,63.6
NetIC5_1: IC5.1 R39.1 | length 1.7
  Top Layer w0.381: R39.1@51.7,31.625 IC5.1@53.406,31.625
NetR2_1: R2.1 X1.A5 | length 6.9
  Top Layer w0.203: v2(21.064,12.884) 21.064,11.856 21.325,11.595 X1.A5@21.325,10.625
  Top Layer w0.381: v2(17.975,12.395) R2.1@17.975,13.32
  Bottom Layer w0.254: v2@17.98,12.395 18.876,13.29 20.657,13.29 v2(21.064,12.884)
NetR3_1: R3.1 X2.P12 | length 2.2
  Bottom Layer w0.381: X2.P12@28.77,62.39 R3.1@30.929,62.391
NetR9_1: R9.1 X2.P6 | length 2.2
  Bottom Layer w0.381: R9.1@24.071,61.375 X2.P6@26.23,61.375
NetR10_1: R10.1 X2.P1 | length 2.2
  Bottom Layer w0.381: R10.1@24.071,51.215 X2.P1@26.23,51.215
NetR13_1: R13.1 X2.P7 | length 2.2
  Bottom Layer w0.381: X2.P7@28.77,50.21 R13.1@30.929,50.21
NetR32_2: R32.2 T6.4 | length 15.1
  Top Layer w0.381: v1(55.7,51.3) R32.2@56.674,51.3 ; v1(57,39.2) 57.049,39.249 57.484,39.249 57.83,39.595 T6.4@58.36,39.595
  Signal Layer 3 w0.381: v1(55.7,51.3) 55.7,40.5 v1(57,39.2)
NetR34_2: R34.2 R35.2 T6.1 T6.2 T6.3 TP13.1 | length 12.1
  Top Layer w0.381: v1(53.5,50.3) R34.2@53.5,51.274
  Signal Layer 3 w0.381: v1(53.5,50.3) 51.8,48.6 51.8,43.25 v1@54.2,40.85
  other v1: 54.2,40.8
NetR43_2: R43.2 X4.2 | length 3.1
  Top Layer w0.254: X4.2@49.5,63.3 50.425,64.226 R43.2@50.425,66
PAIR12: D10.1 D14.2 TP2.1 X2.P13 | length 26.1
  Top Layer w0.508: TP2.1@36.8,46.074 v3(36.8,47.6)
  Top Layer w0.762: v3@36.838,47.61 D10.1@36.838,49.667
  Signal Layer 3 w0.508: X2.P13@19.12,50.71 19.12,48.27 19.79,47.6 v3(36.8,47.6)
  Bottom Layer w0.762: v3@36.838,47.61 D14.2@36.838,49.705
PAIR36: D9.1 D13.2 TP3.1 X2.P14 | length 26.1
  Top Layer w0.508: TP3.1@36.8,60.4 v3(36.8,61.9)
  Top Layer w0.762: v3@36.82,61.86 D9.1@36.82,63.918
  Signal Layer 3 w0.508: X2.P14@19.12,61.89 19.12,63.27 20.215,64.365 34.335,64.365 v3(36.8,61.9)
  Bottom Layer w0.762: v3@36.82,61.835 D13.2@36.82,63.892
PAIR45: D8.1 D12.2 TP4.1 X2.P15 | length 33
  Top Layer w0.508: TP4.1@40.8,46.1 v3(40.8,47.6)
  Top Layer w0.762: v3@40.8,47.46 D8.1@40.8,49.518
  Signal Layer 3 w0.508: X2.P15@17.65,50.71 17.65,47.7 19.025,46.325 39.525,46.325 v3(40.8,47.6)
  Bottom Layer w0.762: v3(40.8,47.6) D12.2@40.8,49.759
PAIR78: D1.1 D11.2 TP5.1 X2.P16 | length 32.8
  Top Layer w0.508: TP5.1@40.9,60.4 v3(40.9,61.9)
  Top Layer w0.762: v3@40.862,61.9 D1.1@40.862,63.768
  Signal Layer 3 w0.508: X2.P16@17.65,61.89 17.65,63.72 19.405,65.475 37.325,65.475 v3(40.9,61.9)
  Bottom Layer w0.762: D11.2@40.862,64.009 40.9,63.971 v3(40.9,61.9)
PME_MODE: IC1.43 TP1.1 | length 10.9
  Top Layer w0.25: IC1.43@25.975,31.85 v2@27.18,31.85
  Top Layer w0.381: v1(34.48,34.6) TP1.1@34.48,35.8
  Bottom Layer w0.25: v2(27.18,31.8) 28.78,33.4 33.28,33.4 v1(34.48,34.6)
PME_N/CONNECT: IC1.22 R8.1 | length 7.8
  Top Layer w0.203: R8.1@13.48,27.025 13.48,27.772 13.808,28.1 17.38,28.1 18.11,28.83 18.11,29.575 18.385,29.85 IC1.22@19.225,29.85
SHIELD: C1.2 C19.2 C36.1 C37.1 C38.1 C41.1 C42.1 C43.1 C71.2 C72.1 C73.1 C74.1 C75.1 H1.0 H2.0 H3.0 H4.0 R1.2 R19.1 R20.1 X1.SH1 X1.SH2 X1.SH3 X1.SH4 X2.S1 X2.S2 | length 6.4
  Top Layer w0.305: 4.25,31.743 R19.1@4.25,32.454
  Signal Layer 3 w1.016: v4(85.7,4) 86.374,4.674 v4(86.374,5.626) 87.326,5.626 v4(88,6.3) 88.953,6.3 v4(89.626,5.626)
  other v1: 10,1 15,1 20,1 25,1 30,1 35,1 40,1 45,1 50,1 55,1 60,1 65,1 70,1 75,1 80,1 85,1 22.5,3 32.5,3 37.5,3 12.5,3.5 10,6 15,6 2.5,7.5 91,8 2.5,12.5 91,13 2.5,17.5 2.5,22.5 91,23 2.5,27.5 91,28 2.5,32.5 91,33 2.5,42.5 91,43 2.5,47.5 91,48 7.5,50 2.5,52.5 91,53 7.5,55 2.374,57.5 90.874,58 7.5,60 2.5,62.5 90.874,63 2.5,67.5 90.874,68 7.5,70 2.5,72.5 90.747,73 9,79 14,79 19,79 24,79 29,79 34,79 39,79 44,79 49,79 54,79 59,79 64,79 69,79 74,79 79,79 84,79
  other v4: 4,1.7 88,1.7 2.374,2.374 5.626,2.374 86.374,2.374 89.626,2.374 1.7,4 6.3,4 90.3,4 2.374,5.626 5.626,5.626 4,6.3 4,73.7 88,73.7 2.374,74.374 5.626,74.374 86.374,74.374 89.626,74.374 1.7,76 6.3,76 85.7,76 90.3,76 2.374,77.626 5.626,77.626 86.374,77.626 89.626,77.626 4,78.3 88,78.3
T2P: D25.1 IC4.20 TP21.1 | length 7.4
  Top Layer w0.254: TP21.1@50.35,69.586 D25.1@50.35,67.6 51.3,66.65 51.3,65 51.5,64.8 52.3,64.8 52.57,64.53 52.57,63.606 IC4.20@52.575,63.6
TEST: IC1.34 R12.1 | length 8.8
  Top Layer w0.203: IC1.34@24.35,28.225 24.35,22.13 24.68,21.8 24.68,20.774 R12.1@25.555,19.9
TR0_N: D6.9 IC1.2 X2.P10 | length 32.9
  Top Layer w0.154: IC1.2@24.85,34.975 24.85,35.402 24.96,35.511 24.96,36.216 25.899,37.156 25.899,41.385 26.741,42.227 26.741,43.279 26.58,43.44 v2(26.58,43.8) 26.58,44.2 26.744,44.364 26.744,46.921 27.204,47.381 30.756,47.381 31.25,47.875 31.25,57.763 29.988,59.025 29.465,59.025 X2.P10@28.77,58.33
  Bottom Layer w0.154: v2(26.58,43.8) 26.58,44.2 26.68,44.3 D6.9@26.68,45.675
TR0_P: D6.1 IC1.1 X2.P11 | length 32.8
  Top Layer w0.154: IC1.1@25.35,34.975 25.35,35.402 25.24,35.511 25.24,36.1 26.18,37.04 26.18,41.269 27.022,42.111 27.022,43.28 27.18,43.438 v2(27.18,43.8) 27.18,44.2 27.025,44.355 27.025,46.805 27.32,47.1 30.872,47.1 31.531,47.759 31.531,57.961 30.227,59.265 30.03,59.462 X2.P11@28.951,60.541
  Bottom Layer w0.154: D6.1@27.08,44.725 27.08,44.3 27.18,44.2 v2(27.18,43.8) ; X2.P11@28.77,60.36 X2.P11@29.008,60.122
TR1_N: D6.5 IC1.5 X2.P5 | length 36.6
  Top Layer w0.154: IC1.5@23.35,34.975 23.35,35.402 23.46,35.511 23.46,36.641 23.699,36.88 23.699,43.281 23.58,43.4 v2(23.58,43.8) 23.58,44.2 23.75,44.37 23.75,47.882 24.384,48.516 29.842,48.516 30.277,48.95 30.277,55.903 29.88,56.3 26.964,56.3 25.475,56.3 25.2,56.575 25.2,58.315 X2.P5@26.23,59.345
  Bottom Layer w0.154: v2(23.58,43.8) 23.58,44.2 23.68,44.3 D6.5@23.68,44.725
TR1_P: D6.6 IC1.4 X2.P4 | length 34
  Top Layer w0.154: IC1.4@23.85,34.975 23.85,35.402 23.74,35.511 23.74,36.524 23.98,36.764 23.98,43.2 24.18,43.4 v2(24.18,43.8) 24.18,44.2 24.031,44.349 24.031,47.766 24.5,48.235 29.958,48.235 30.558,48.834 30.558,56.019 29.996,56.581 26.964,56.581 X2.P4@26.23,57.315
  Bottom Layer w0.154: D6.6@24.08,45.675 24.08,44.3 24.18,44.2 v2(24.18,43.8)
TR2_N: D7.9 IC1.8 X2.P2 | length 27
  Top Layer w0.154: IC1.8@21.85,34.975 21.85,35.402 21.96,35.512 21.96,36.238 21.58,36.618 21.58,41.705 22.242,42.367 22.242,43.242 22.08,43.405 v2(22.08,43.8) 22.08,44.2 22.244,44.364 22.244,48.908 22.917,49.581 26.994,49.581 27.263,49.85 27.263,53.669 27.082,53.85 26.825,53.85 X2.P2@26.23,53.255
  Bottom Layer w0.154: v2(22.08,43.8) 22.08,44.2 22.18,44.3 D7.9@22.18,45.675
TR2_P: D7.1 IC1.7 X2.P3 | length 27.1
  Top Layer w0.154: IC1.7@22.35,34.975 22.35,35.402 22.24,35.511 22.24,36.354 21.861,36.734 21.861,41.588 22.523,42.251 22.523,43.269 22.68,43.426 v2(22.68,43.8) 22.68,44.2 22.525,44.355 22.525,48.791 23.034,49.3 27.11,49.3 27.544,49.734 27.544,53.669 27.544,53.981 27.544,54.283 26.542,55.285 X2.P3@26.23,55.285
  Bottom Layer w0.154: D7.1@22.58,44.725 22.58,44.3 22.68,44.2 v2(22.68,43.8)
TR3_N: D7.5 IC1.11 X2.P9 | length 28.3
  Top Layer w0.154: v2(19.08,43.8) 19.08,43.407 19.24,43.248 19.24,36.94 20.46,35.72 20.46,35.512 20.35,35.402 IC1.11@20.35,34.975
  Bottom Layer w0.154: v2(19.08,43.8) 19.08,44.2 19.18,44.3 D7.5@19.18,44.725 ; D7.5@19.175,44.725 19.175,45.675 19.175,47.957 19.377,48.158 19.734,48.516 27.069,48.516 27.394,48.841 27.394,52.675 27.394,53.094 27.678,53.378 28.57,54.27 X2.P9@28.77,54.27
TR3_P: D7.6 IC1.10 X2.P8 | length 28
  Top Layer w0.154: v2(19.68,43.8) 19.68,43.421 19.52,43.261 19.52,37.056 20.74,35.837 20.74,35.511 20.85,35.402 IC1.10@20.85,34.975
  Bottom Layer w0.154: D7.6@19.575,45.675 19.575,47.96 19.85,48.235 27.185,48.235 27.675,48.725 27.675,52.675 27.675,52.969 27.881,53.175 28.11,53.175 28.77,52.515 X2.P8@28.77,52.24 ; D7.6@19.58,45.675 19.58,44.3 19.68,44.2 v2(19.68,43.8)
USB2D1_N: D4.2 D4.5 L5.4 X1.A7 X1.B7 | length 8.7
  Top Layer w0.206: X1.A7@22.325,10.68 22.325,11.383 22.275,11.433 22.275,13.725 22.275,14.675 22.275,15.646 22.575,15.946 L5.4@22.575,16.25
  Bottom Layer w0.206: X1.B7@21.675,9.375 21.675,9.889 21.953,10.166 21.953,10.992 22.359,11.399 v2@22.359,12.122
  other v2: 22.359,12.177
USB2D1_P: D4.1 D4.6 L5.1 X1.A6 X1.B6 | length 10.2
  Top Layer w0.206: L5.1@21.575,16.25 21.575,15.96 21.875,15.66 21.875,11.433 21.825,11.383 X1.A6@21.825,10.68
  Bottom Layer w0.206: v2(21.8,12.685) 22.588,12.685 22.816,12.456 22.816,11.385 22.296,10.865 22.296,10.051 22.475,9.872 X1.B6@22.475,9.375
USB2D_N: IC1.27 L5.3 | length 11.3
  Top Layer w0.206: v2(20.08,22.2) 19.88,22.4 19.88,26.1 20.766,26.986 20.766,27.689 20.85,27.772 IC1.27@20.85,28.225 ; v2@22.246,20.7 22.246,19.534 22.58,19.2 L5.3@22.58,18.95
  Bottom Layer w0.206: v2(20.08,22.2) 20.08,21.985 20.523,21.543 21.437,21.543 v2(22.28,20.7)
USB2D_P: IC1.26 L5.2 | length 11.5
  Top Layer w0.206: v2@19.547,21.8 19.547,26.238 19.68,26.371 ; 19.647,26.338 19.68,26.371 ; IC1.26@20.35,28.225 20.35,27.772 20.434,27.688 20.434,27.124 19.68,26.371 ; L5.2@21.58,18.95 21.58,19.2 21.914,19.534 21.914,20.266 v2(21.68,20.5)
  Bottom Layer w0.206: v2(19.58,21.8) 19.795,21.8 20.385,21.21 21.28,21.21 21.68,20.81 v2(21.68,20.5)
USB3RX1_N: D3.2 D3.5 L3.4 X1.B11 | length 19.1
  Top Layer w0.206: v2(24.36,12.635) 24.269,12.726 24.269,15.541 24.425,15.697 L3.4@24.425,16.025
  Signal Layer 3 w0.206: X1.B11@19.675,8.675 19.675,8.145 19.893,7.927 19.893,6.252 20.418,5.727 25.023,5.727 25.408,6.111 25.408,8.643 25.765,9 25.765,10.932 24.366,12.332 v2@24.366,12.63
USB3RX1_P: D3.1 D3.6 L3.1 X1.B10 | length 19.8
  Top Layer w0.206: L3.1@23.675,16.025 23.675,15.697 23.869,15.503 23.869,13.675 v2@23.869,12.122
  Signal Layer 3 w0.206: X1.B10@20.475,8.675 20.475,8.145 20.225,7.895 20.225,6.39 20.556,6.059 22.511,6.059 22.594,6.059 22.717,6.183 22.717,6.444 22.841,6.567 23.005,6.567 23.129,6.444 23.129,6.183 23.252,6.059 23.417,6.059 23.54,6.183 23.54,6.444 23.664,6.567 23.828,6.567 23.952,6.444 23.952,6.183 24.075,6.059 24.886,6.059 25.075,6.249 25.075,8.781 25.432,9.138 25.432,10.795 24.105,12.122 v2@23.807,12.122
  other v2: 23.801,12.127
